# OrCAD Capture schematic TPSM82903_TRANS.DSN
size E; title: TPSM82903, 3-V to 17-V, High Efficiency and Low IQ Buck; rev: 1.0; note: Datasheet: SLVSG64                    EVM: SNVU796; note: Synchronous Step Down Converter
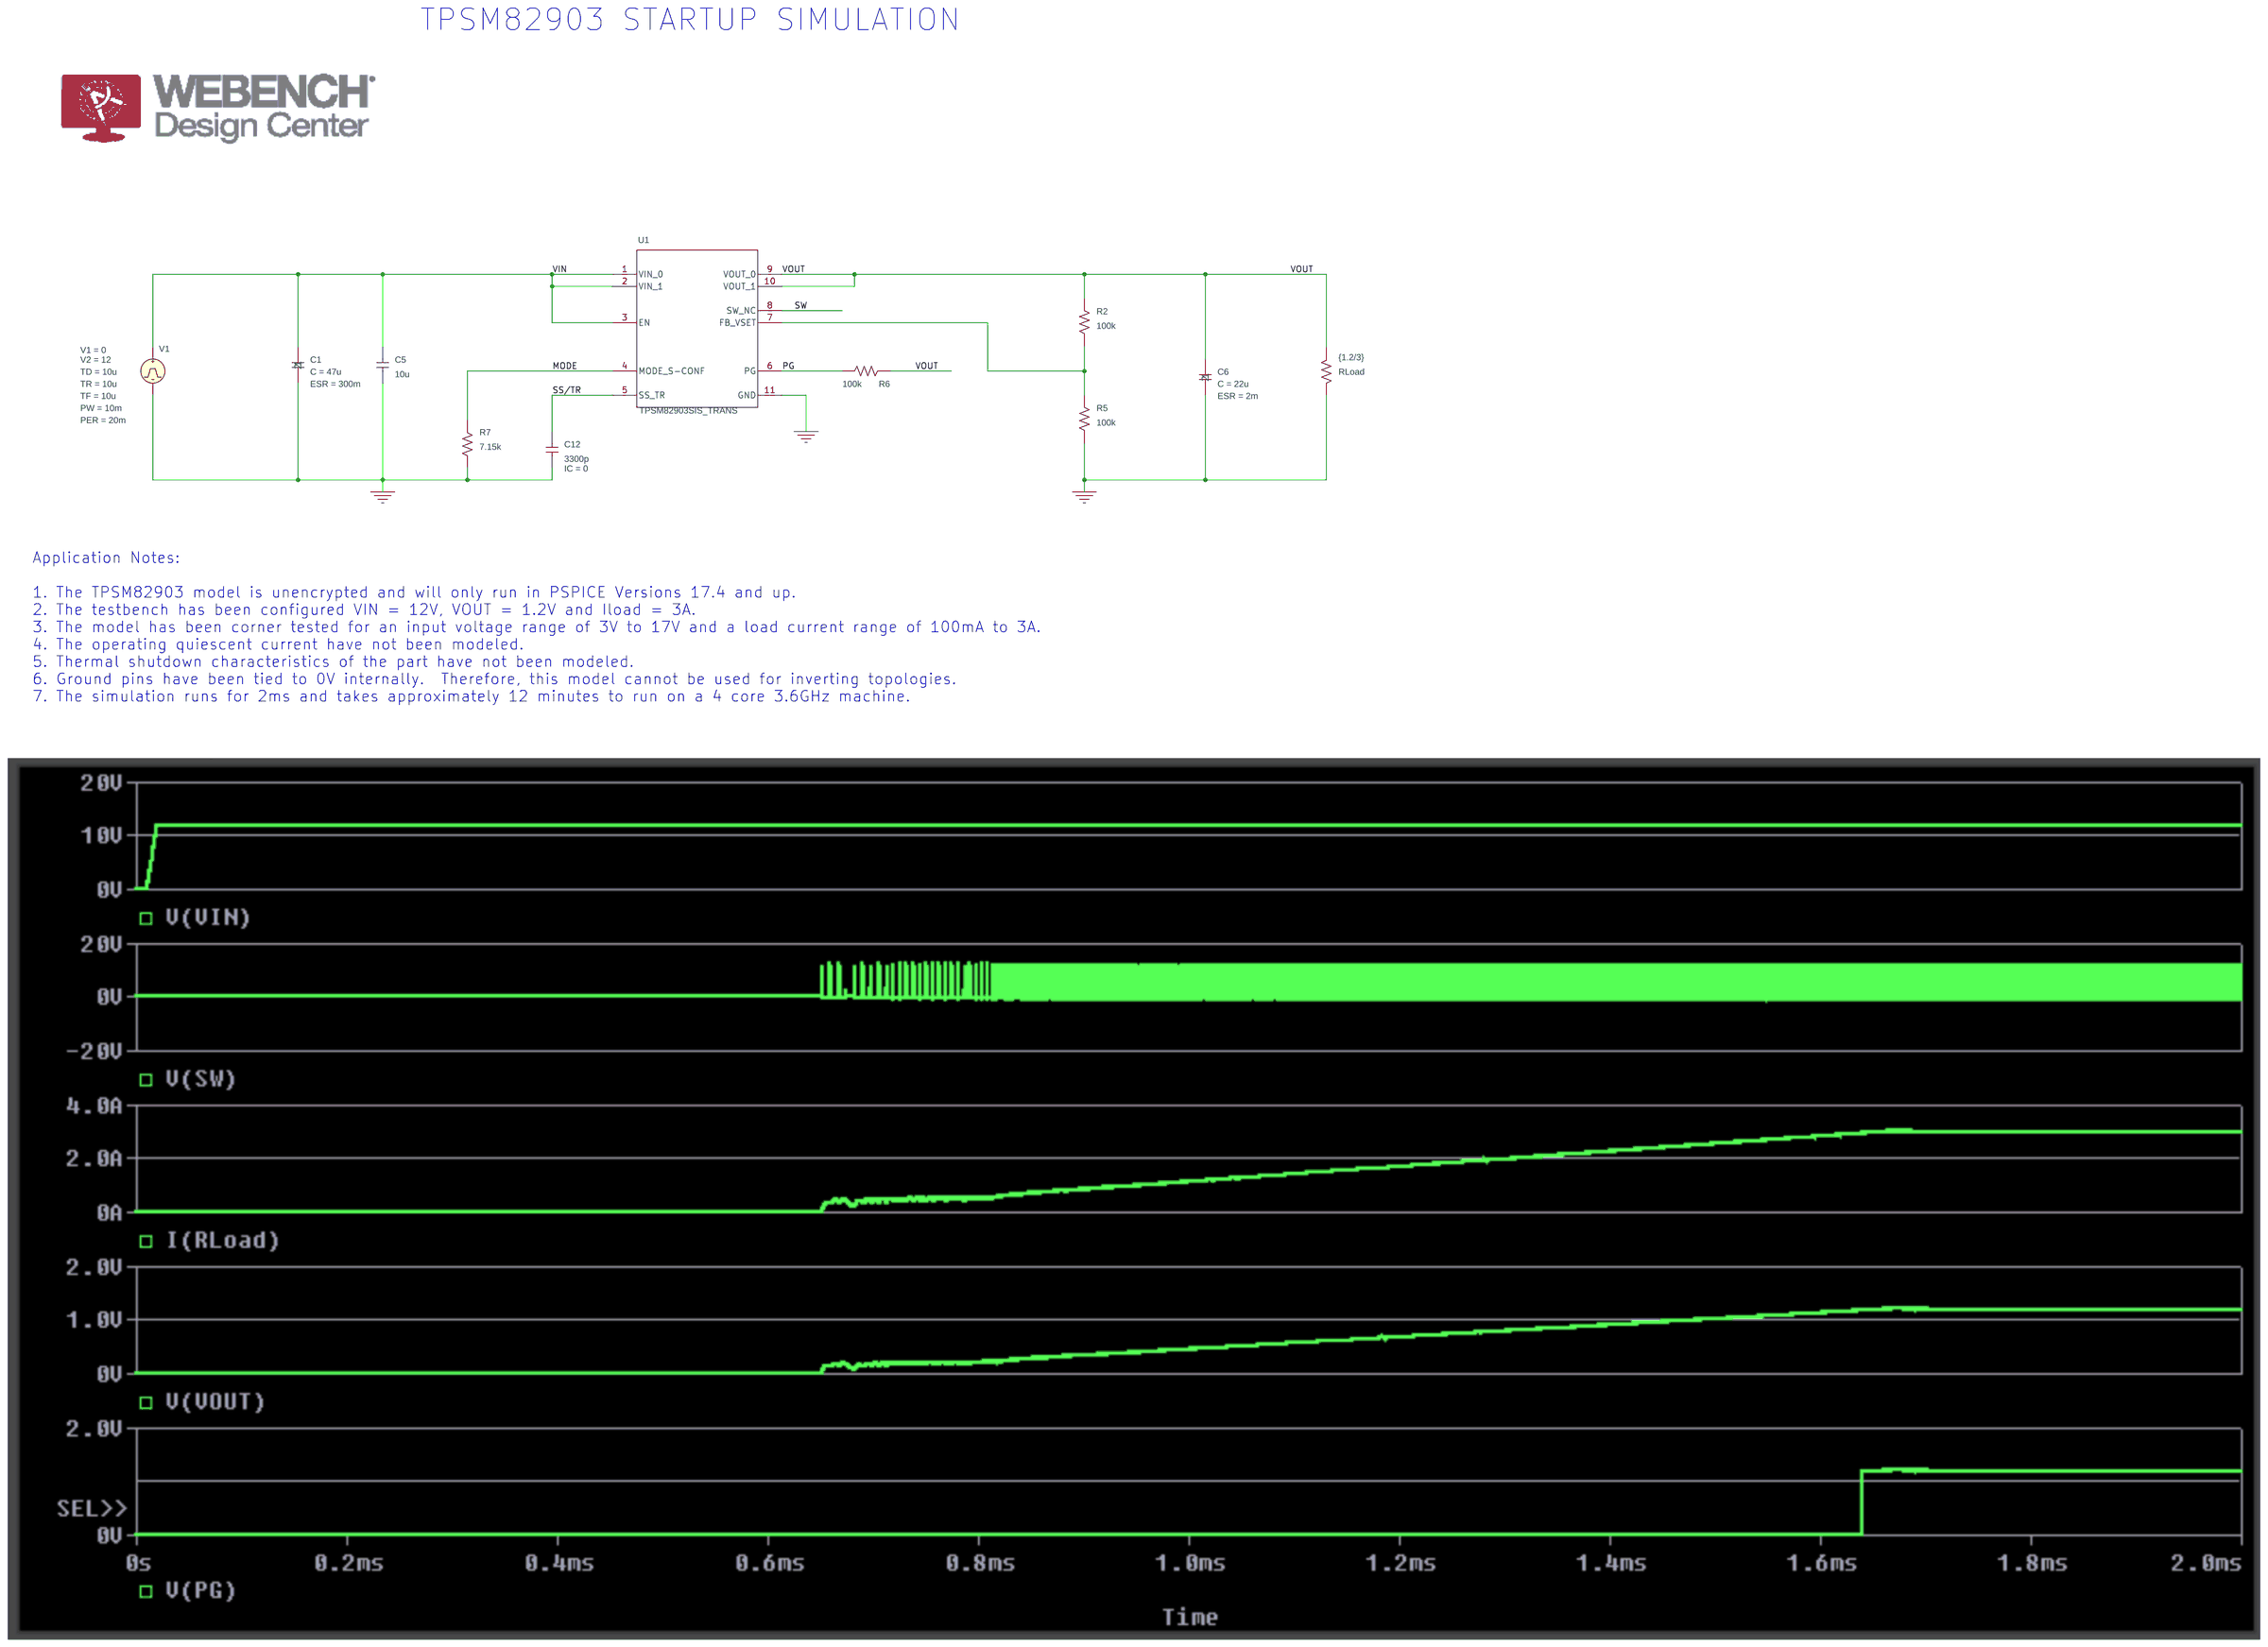
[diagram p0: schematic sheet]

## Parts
C1  CESR
C5  10u  [RAD/CK05]
C6  CESR
C12  3300p  [RAD/CK05]
R2  100k  [AX/RC05]
R5  100k  [AX/RC05]
R6  100k  [AX/RC05]
R7  7.15k  [AX/RC05]
RLoad  {1.2/3}  [AX/RC05]
U1  TPSM82903SIS_TRANS  [SIS0011A-MFG]
V1  VPULSE

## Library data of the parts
C1 = CESR_1: C: 47u; ESR: 300m; IC: 0; PSpiceTemplate: X^@REFDES %1 %2 @MODEL PARAMS: ?C|C=@C||C=10U| ?ESR|ESR=@ESR||ESR=2M| ?IC|IC=@IC||IC=1N| ?X|X=@X||X=1|; X: 1
C5 = C
C6 = CESR: C: 22u; ESR: 2m; IC: 0; PSpiceTemplate: X^@REFDES %1 %2 @MODEL PARAMS: ?C|C=@C||C=10U| ?ESR|ESR=@ESR||ESR=2M| ?IC|IC=@IC||IC=1N| ?X|X=@X||X=1|; X: 1
C12 = C: IC: 0
R2 R5-R7 RLoad = R
U1 = TPSM82903SIS_TRANS
V1 = VPULSE: PER: 20m; PW: 10m; TD: 10u; TF: 10u; TR: 10u; V1: 0; V2: 12

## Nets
VIN: C1.1 C5.1 U1.1(VIN_0) U1.2(VIN_1) U1.3(EN) V1.1(+)
0: C1.2 C5.2 C6.2 C12.2 R5.1 R7.2 RLoad.2 U1.11(GND) V1.2(-)
MODE: R7.1 U1.4(MODE_S-CONF)
PG: R6.2 U1.6(PG)
SS/TR: C12.1 U1.5(SS_TR)
SW: U1.8(SW_NC)
VOUT: C6.1 R2.2 R6.1 RLoad.1 U1.9(VOUT_0) U1.10(VOUT_1)
N16781534: R2.1 R5.2 U1.7(FB_VSET)

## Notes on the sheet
- TPSM82903 STARTUP SIMULATION
- Application Notes:
  1. The TPSM82903 model is unencrypted and will only run in PSPICE Versions 17.4 and up.
  2. The testbench has been configured VIN = 12V, VOUT = 1.2V and Iload = 3A.
  3. The model has been corner tested for an input voltage range of 3V to 17V and a load current range of 100mA to 3A.
  4. The operating quiescent current have not been modeled.
  5. Thermal shutdown characteristics of the part have not been modeled.
  6. Ground pins have been tied to 0V internally.  Therefore, this model cannot be used for inverting topologies.
  7. The simulation runs for 2ms and takes approximately 12 minutes to run on a 4 core 3.6GHz machine.
